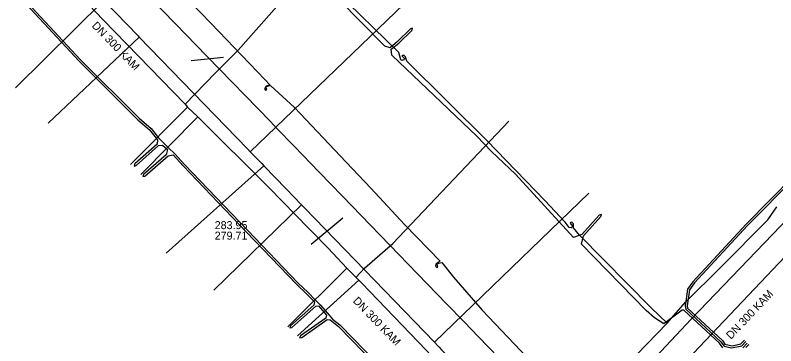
# Model space of a CAD drawing. Extents: x -598233 to -596890, y -1157848 to -1156431.
# Drawn here: x -597732.3 to -597656.3, y -1156677.4 to -1156644.4 of the extents above; entities that cross this region are included whole.
import ezdxf

# ---------------------------------------------------------------- set-up
doc = ezdxf.new("R2010")
doc.units = 0
for name, color, linetype in [('Vrstva 1', 7, 'Continuous'), ('Vrstva 13', 7, 'Continuous'), ('Vrstva 19', 7, 'Continuous'), ('Vrstva 42', 7, 'Continuous'), ('Vrstva 5', 7, 'Continuous'), ('Vrstva 55', 7, 'Continuous'), ('Vrstva 8', 7, 'Continuous')]:
    doc.layers.add(name, color=color, linetype=linetype)

msp = doc.modelspace()

# ---------------------------------------------------------------- linework, layer by layer
at = {"layer": 'Vrstva 1'}
for points in [[(-597711.53, -1156648.6), (-597714.747, -1156648.932)], [(-597702.76, -1156667.28), (-597699.583, -1156664.645)]]:
    msp.add_lwpolyline(points, dxfattribs=at)
at = {"layer": 'Vrstva 13'}
for points in [[(-597720.347, -1156641.064), (-597716.312, -1156645.237), (-597713.18, -1156648.48), (-597706.842, -1156655.023), (-597706.23, -1156655.66), (-597704.472, -1156657.462), (-597701.95, -1156660.089), (-597699.63, -1156662.49), (-597693.08, -1156669.26), (-597689.228, -1156673.253), (-597687.485, -1156675.057), (-597686.04, -1156676.55), (-597679.97, -1156682.82), (-597677.82, -1156685.05), (-597676.07, -1156686.72)], [(-597640.47, -1156643.98), (-597640.13, -1156648.9), (-597648.55, -1156657.86), (-597656.67, -1156666.32), (-597664.78, -1156674.78), (-597668.83, -1156679.06), (-597674.794, -1156686.422), (-597675.175, -1156686.856)]]:
    msp.add_lwpolyline(points, dxfattribs=at)
at = {"layer": 'Vrstva 19'}
for points in [[(-597715.37, -1156653.28), (-597712.34, -1156650.19), (-597710.06, -1156647.86), (-597700.8, -1156637.38)], [(-597729.224, -1156638.888), (-597723.54, -1156644.844), (-597715.37, -1156653.28), (-597715.11, -1156653.56), (-597714.1, -1156654.549), (-597706.956, -1156661.643), (-597703.002, -1156665.705), (-597702.687, -1156665.996), (-597701.076, -1156667.665), (-597699.19, -1156669.66), (-597698.29, -1156670.58), (-597697.99, -1156670.88), (-597697.71, -1156671.159), (-597691.257, -1156677.883), (-597686.623, -1156682.855), (-597682.336, -1156687.154), (-597677.647, -1156692.554), (-597677.292, -1156692.774), (-597676.824, -1156693.061), (-597671.659, -1156696.477), (-597663.57, -1156702.51), (-597662.21, -1156703.5), (-597652.381, -1156710.707)], [(-597715.11, -1156653.56), (-597720.83, -1156659.31)], [(-597714.1, -1156654.549), (-597719.79, -1156660.31)], [(-597698.29, -1156670.58), (-597698.279, -1156670.568), (-597697.44, -1156669.69), (-597694.59, -1156667.2), (-597683.01, -1156654.97)], [(-597705.11, -1156675.54), (-597699.19, -1156669.66)], [(-597697.99, -1156670.88), (-597704.12, -1156676.45)]]:
    msp.add_lwpolyline(points, dxfattribs=at)
at = {"layer": 'Vrstva 42'}
for points in [[(-597731.099, -1156643.129), (-597725.808, -1156648.831), (-597719.952, -1156654.686), (-597718.757, -1156655.7), (-597718.021, -1156656.649), (-597717.403, -1156657.276), (-597717.013, -1156657.626), (-597716.385, -1156658.234), (-597715.417, -1156659.322), (-597709.118, -1156665.891), (-597704.1, -1156671.139), (-597703.05, -1156672.119), (-597702.348, -1156672.84), (-597701.855, -1156673.334), (-597701.125, -1156674.174), (-597700.628, -1156674.762), (-597699.883, -1156675.356), (-597693.608, -1156681.801)], [(-597661.621, -1156677.656), (-597661.967, -1156677.167), (-597665.511, -1156673.884), (-597665.68, -1156673.88), (-597667.53, -1156675.23), (-597668.45, -1156674.65), (-597669.27, -1156673.92), (-597675.76, -1156667.28), (-597675.552, -1156666.448), (-597673.819, -1156664.516), (-597673.76, -1156664.3), (-597673.968, -1156664.382), (-597675.7, -1156666.313), (-597676.54, -1156666.62), (-597682.34, -1156660.26), (-597684.74, -1156658.02), (-597686.22, -1156656.46), (-597694.71, -1156648.38), (-597694.751, -1156647.792), (-597693.993, -1156647.175), (-597692.693, -1156645.901), (-597692.62, -1156645.69), (-597692.833, -1156645.758), (-597694.127, -1156647.025), (-597694.876, -1156647.636), (-597695.4, -1156647.48), (-597700.04, -1156642.74)], [(-597641.582, -1156643.208), (-597641.917, -1156645.581), (-597643.126, -1156648.187), (-597644.736, -1156650.215), (-597645.896, -1156651.475), (-597648.035, -1156654.134), (-597652.797, -1156659.135), (-597654.546, -1156660.485), (-597659.302, -1156665.271), (-597664.618, -1156671.027), (-597665.146, -1156671.783), (-597665.209, -1156672.266), (-597665.391, -1156673.431), (-597665.331, -1156673.778), (-597661.81, -1156677.04), (-597661.5, -1156677.48), (-597660.75, -1156677.63), (-597659.731, -1156677.443), (-597659.315, -1156677.02)], [(-597641.378, -1156643.192), (-597641.723, -1156645.639), (-597642.954, -1156648.293), (-597644.584, -1156650.345), (-597645.744, -1156651.605), (-597647.885, -1156654.266), (-597652.663, -1156659.284), (-597654.414, -1156660.635), (-597659.158, -1156665.409), (-597664.462, -1156671.153), (-597664.954, -1156671.857), (-597665.011, -1156672.294), (-597665.189, -1156673.429), (-597665.146, -1156673.677), (-597661.653, -1156676.913), (-597661.417, -1156677.292), (-597660.7, -1156677.432), (-597659.829, -1156677.258), (-597659.458, -1156676.88)], [(-597731.24, -1156643.271), (-597725.952, -1156648.969), (-597720.088, -1156654.834), (-597718.903, -1156655.84), (-597718.116, -1156656.852), (-597718.163, -1156657.26)], [(-597718.163, -1156657.26), (-597720.369, -1156659.252), (-597720.45, -1156659.46), (-597720.235, -1156659.4), (-597718.015, -1156657.396), (-597717.607, -1156657.362), (-597717.107, -1156657.81), (-597717.238, -1156658.33), (-597719.515, -1156660.313), (-597719.6, -1156660.52), (-597719.383, -1156660.464), (-597717.068, -1156658.448), (-597716.57, -1156658.327), (-597715.563, -1156659.458), (-597709.262, -1156666.029), (-597704.24, -1156671.281), (-597703.19, -1156672.261), (-597702.438, -1156673.035), (-597702.488, -1156673.388), (-597704.826, -1156675.443), (-597704.91, -1156675.65), (-597704.694, -1156675.593), (-597702.301, -1156673.49), (-597702.04, -1156673.426), (-597701.225, -1156674.363), (-597701.29, -1156674.677), (-597703.824, -1156676.453), (-597703.93, -1156676.65), (-597703.709, -1156676.617), (-597701.153, -1156674.825), (-597700.857, -1156674.835), (-597700.017, -1156675.504), (-597693.752, -1156681.939)], [(-597659.173, -1156677.16), (-597659.633, -1156677.629)], [(-597659.03, -1156677.3), (-597659.33, -1156677.606)]]:
    msp.add_lwpolyline(points, dxfattribs=at)
at = {"layer": 'Vrstva 5'}
for p, q in [((-597732.3, -1156651.64), (-597723.482, -1156642.916)), ((-597693.49, -1156643.26), (-597708.859, -1156658.03)), ((-597729.04, -1156655.17), (-597719.956, -1156646.56)), ((-597717.24, -1156668.18), (-597707.482, -1156659.453)), ((-597675.01, -1156662.19), (-597690.448, -1156677.091)), ((-597712.48, -1156671.88), (-597703.715, -1156663.351))]:
    msp.add_line(p, q, dxfattribs=at)
for points in [[(-597732.34, -1156633.76), (-597723.913, -1156642.47), (-597723.899, -1156642.485), (-597723.566, -1156642.829), (-597723.482, -1156642.916), (-597720.064, -1156646.449), (-597719.956, -1156646.56), (-597709.133, -1156657.747), (-597708.859, -1156658.03), (-597707.704, -1156659.224), (-597707.482, -1156659.453), (-597705.27, -1156661.74)], [(-597637.54, -1156649.63), (-597647.966, -1156660.649), (-597648.071, -1156660.76), (-597667.62, -1156681.42)], [(-597705.27, -1156661.74), (-597703.715, -1156663.351), (-597703.41, -1156663.666), (-597690.448, -1156677.091), (-597690.099, -1156677.452), (-597689.975, -1156677.58), (-597689.725, -1156677.839), (-597677.5, -1156690.5)]]:
    msp.add_lwpolyline(points, dxfattribs=at)
at = {"layer": 'Vrstva 55'}
for points in [[(-597714.881, -1156643.008), (-597712.76, -1156645.21), (-597707.402, -1156650.814), (-597706.9, -1156651.34), (-597707.25, -1156651.48), (-597707.41, -1156651.75), (-597707.3, -1156651.9), (-597707.19, -1156651.74), (-597707.28, -1156651.63), (-597707.21, -1156651.51), (-597706.91, -1156651.4), (-597706.79, -1156651.43), (-597704.44, -1156653.61), (-597699.262, -1156659.066), (-597696.8, -1156661.66), (-597693.44, -1156665.3), (-597689.86, -1156668.99), (-597690.28, -1156669.25), (-597690.34, -1156669.47), (-597690.18, -1156669.63), (-597690.11, -1156669.43), (-597690.22, -1156669.31), (-597689.99, -1156669.17), (-597689.71, -1156669.12), (-597688.52, -1156670.58), (-597685.68, -1156673.86), (-597681.17, -1156678.6)], [(-597671.23, -1156679.37), (-597667.19, -1156675.17), (-597668.79, -1156673.64), (-597675.95, -1156666.36), (-597676.53, -1156665.63), (-597676.53, -1156665.41), (-597676.56, -1156665.23), (-597676.71, -1156665.08), (-597676.84, -1156665.11), (-597676.88, -1156665.19), (-597676.76, -1156665.34), (-597676.65, -1156665.48), (-597676.67, -1156665.59), (-597676.79, -1156665.65), (-597676.98, -1156665.62), (-597677.36, -1156665.06), (-597679.421, -1156662.918), (-597685.18, -1156656.93), (-597693.19, -1156648.98), (-597693.33, -1156648.55), (-597693.46, -1156648.42), (-597693.62, -1156648.41), (-597693.7, -1156648.45), (-597693.56, -1156648.58), (-597693.45, -1156648.71), (-597693.5, -1156648.85), (-597693.69, -1156648.91), (-597693.8, -1156648.84), (-597694, -1156648.11), (-597695.296, -1156646.849), (-597699.07, -1156643.18)], [(-597671.52, -1156679.06), (-597671.23, -1156679.37), (-597667.19, -1156675.17), (-597665.34, -1156673.06), (-597661.86, -1156669.61), (-597657.12, -1156664.83), (-597656.23, -1156663.54)]]:
    msp.add_lwpolyline(points, dxfattribs=at)

# ---------------------------------------------------------------- texts
at = {"layer": 'Vrstva 8'}
for rotation, p in [(314.05296, (-597724.736, -1156645.484)), (46.58317, (-597660.803, -1156676.846)), (313.99669, (-597698.644, -1156673.009))]:
    msp.add_text('DN 300 KAM', height=0.8, rotation=rotation, dxfattribs=at).set_placement(p)
for s, p in [('283.95', (-597712.404, -1156665.774)), ('279.71', (-597712.404, -1156666.824))]:
    msp.add_text(s, height=0.8, dxfattribs=at).set_placement(p)

doc.saveas('drawing.dxf')
